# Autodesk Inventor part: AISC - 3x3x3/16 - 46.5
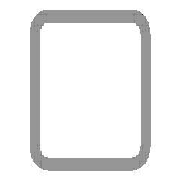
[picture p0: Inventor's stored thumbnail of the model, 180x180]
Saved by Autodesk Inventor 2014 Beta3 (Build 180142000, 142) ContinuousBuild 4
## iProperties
IsCustomPart: 1
_CCFamilyMember: 9
_CCFamilyDisplayName: ANSI AISC (Square) - Tube
_FrameMemberDoc: Frame Member File
_Version: 15.0.0
_GetPNFromCC: 1
Created: 2011-01
Part Number: AISC - 3x3x3/16 - 46.5
Material: Steel, Mild
Description: Tube
Document SubType Name: Modeling
Standard: ANSI
Designer: Beta-8540w
Standards Organization: ANSI
Language: en-US
Size Designation: 3x3x3/16
Categories: <MemberInstance><Categories><Category DisplayName="Structural Shapes" InternalName="089c4875-fa83-4c05-b084-43b9cc11f5ed" Mnemonic="GRDR"><CategoryParameter Dis
Stock Number: 3x3x3/16
Density: 7.86 g/cm^3
Appearance: Steel
G_W: 3.000 in
G_H: 3.000 in
G_L: 46.500 in
Author: Beta-8540w
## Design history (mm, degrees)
node "Start plane"
node "End plane"
sketch "Sketch"
  geometry: L1 (-38.1, -28.575)-(-38.1, 28.575); L2 (-28.575, 38.1)-(28.575, 38.1); L3 (38.1, 28.575)-(38.1, -28.575); L4 (28.575, -38.1)-(-28.575, -38.1); L5 (-28.575, 33.337)-(28.575, 33.338); L6 (33.338, 28.575)-(33.338, -28.575); L7 (28.575, -33.337)-(-28.575, -33.338); L8 (-33.338, -28.575)-(-33.338, 28.575); L9 (0, 56.102)-(0, -56.102) reference; L10 (-56.102, 0)-(56.102, 0) reference; A1 r 9.525 centre (-28.575, -28.575) between (-38.1, -28.575) and (-28.575, -38.1); A2 r 9.525 centre (-28.575, 28.575) between (-28.575, 38.1) and (-38.1, 28.575); A3 r 9.525 centre (28.575, 28.575) between (38.1, 28.575) and (28.575, 38.1); A4 r 9.525 centre (28.575, -28.575) between (28.575, -38.1) and (38.1, -28.575); A5 r 4.763 centre (-28.575, 28.575) between (-28.575, 33.337) and (-33.338, 28.575); A6 r 4.763 centre (28.575, 28.575) between (33.338, 28.575) and (28.575, 33.338); A7 r 4.763 centre (28.575, -28.575) between (28.575, -33.337) and (33.338, -28.575); A8 r 4.763 centre (-28.575, -28.575) between (-33.338, -28.575) and (-28.575, -33.338)
  constraints: 16 end point, 16 point on circle, 8 centre point, 8 tangent, 4 parallel, 3 equal radius, 2 perpendicular, 7 other
  dimensions: "d10" = 76.2 distance between parallel lines of L2 L4 (= G_H); "d11" = 76.2 distance between parallel lines of L1 L3 (= G_W); "d12" = 4.7625 distance between parallel lines of L3 L6 (= G_T); "d15" = 38.1 distance between parallel lines of L2 L10 (= 0.5 x d10); "d16" = 38.1 distance between parallel lines of L9 L3 (= 0.5 x d11); "d17" = 9.525 radius of A1 (= G_IR)
extrude "Body" new body sketch "Sketch" stored distance "d3" = 1181.1 (= G_L); taper "d4" = 0 deg
node "Driven Length"
  sketch "Sketch3"
    geometry: L1 (0, 0)-(10, 0) reference
    constraints: 2 end point, 1 horizontal
  workplane "Work Plane3"
  sketch "Sketch4"
    geometry: L1 (-2, 38.1)-(12, 38.1) reference; L2 (-2, 1219.2)-(12, 1219.2) reference
    dimensions: "d19" = 1181.1 distance between parallel lines of L1 L2 (derived)
workplane "Work Plane4"
split "Split1"
body "Solid1"
other parameters: "G_W" = 76.2 [user parameter; used in 1 equation term], "G_H" = 76.2 [user parameter; used in 1 equation term], "G_T" = 4.7625 [user parameter; used in 1 equation term], "G_IR" = 9.525 [user parameter; used in 1 equation term], "G_L" = 1181.1 (= d19) [user parameter; used in 1 equation term], "G_OFFSET_START" = -38.1 [user parameter; used in 1 equation term], "G_OFFSET_END" = 0 [user parameter; used in 1 equation term], "d13" = 38.1 (= -G_OFFSET_START), "d14" = 1219.2 (= G_OFFSET_END + B_L), "B_L" = 1219.2 [user parameter; used in 1 equation term], "d18" = 90 deg
